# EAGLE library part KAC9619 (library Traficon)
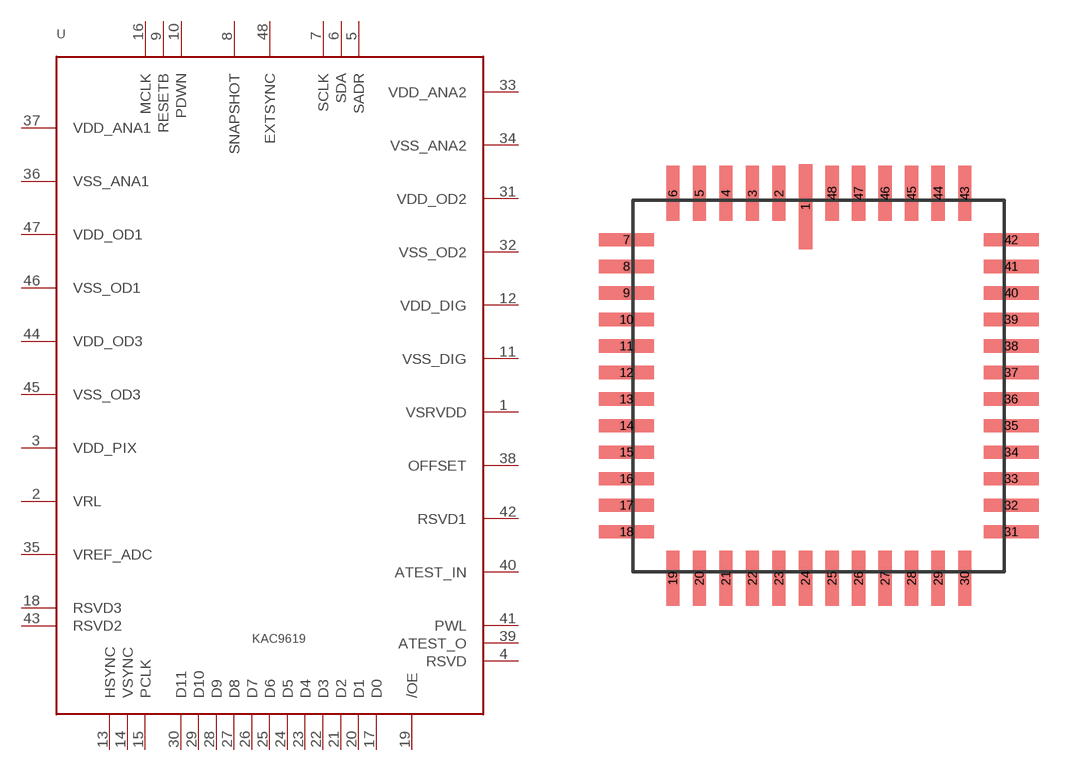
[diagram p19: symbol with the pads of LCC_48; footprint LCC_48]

Designator prefix U

## KAC9619  [LCC_48]
1  VSRVDD  pas
2  VRL  pas
3  VDD_PIX  pas
4  RSVD  pas
5  SADR  in
6  SDA
7  SCLK  in
8  SNAPSHOT  in
9  RESETB  in
10  PDWN  in
11  VSS_DIG  pas
12  VDD_DIG  pas
13  HSYNC  out
14  VSYNC  out
15  PCLK  out
16  MCLK  in
17  D0  out
18  RSVD3  pas
19  /OE  in
20  D1  out
21  D2  out
22  D3  out
23  D4  out
24  D5  out
25  D6  out
26  D7  out
27  D8  out
28  D9  out
29  D10  out
30  D11  out
31  VDD_OD2  pas
32  VSS_OD2  pas
33  VDD_ANA2  pas
34  VSS_ANA2  pas
35  VREF_ADC  pas
36  VSS_ANA1  pas
37  VDD_ANA1  pas
38  OFFSET  pas
39  ATEST_O  pas
40  ATEST_IN  pas
41  PWL  pas
42  RSVD1  pas
43  RSVD2  pas
44  VDD_OD3  pas
45  VSS_OD3  pas
46  VSS_OD1  pas
47  VDD_OD1  pas
48  EXTSYNC  out

## Footprint LCC_48 (pad centres in mm)
smd 0.508 x 3.251: 1 -0.508,6.858
smd 0.508 x 2.108: 2 -1.524,7.366; 3 -2.54,7.366; 4 -3.556,7.366; 5 -4.572,7.366; 6 -5.588,7.366; 19 -5.588,-7.366; 20 -4.572,-7.366; 21 -3.556,-7.366; 22 -2.54,-7.366; 23 -1.524,-7.366; 24 -0.508,-7.366; 25 0.508,-7.366; 26 1.524,-7.366; 27 2.54,-7.366; 28 3.556,-7.366; 29 4.572,-7.366; 30 5.588,-7.366; 43 5.588,7.366; 44 4.572,7.366; 45 3.556,7.366; 46 2.54,7.366; 47 1.524,7.366; 48 0.508,7.366
smd 2.108 x 0.508: 7 -7.366,5.588; 8 -7.366,4.572; 9 -7.366,3.556; 10 -7.366,2.54; 11 -7.366,1.524; 12 -7.366,0.508; 13 -7.366,-0.508; 14 -7.366,-1.524; 15 -7.366,-2.54; 16 -7.366,-3.556; 17 -7.366,-4.572; 18 -7.366,-5.588; 31 7.366,-5.588; 32 7.366,-4.572; 33 7.366,-3.556; 34 7.366,-2.54; 35 7.366,-1.524; 36 7.366,-0.508; 37 7.366,0.508; 38 7.366,1.524; 39 7.366,2.54; 40 7.366,3.556; 41 7.366,4.572; 42 7.366,5.588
